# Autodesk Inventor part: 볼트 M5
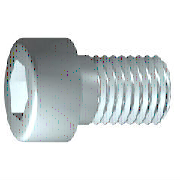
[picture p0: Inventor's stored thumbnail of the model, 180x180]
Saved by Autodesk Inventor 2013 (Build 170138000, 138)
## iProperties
IsCustomPart: 0
Created: 2015-11
Part Number: 볼트 M5
Material: 스테인리스강
Description: 6각머리 태핑 나사
Document SubType Name: Modeling
Standard: KS B 1003
Designer: mdu
Standards Organization: KS
Language: ko-KR
Size Designation: M 5 x 20
Categories: <MemberInstance><Categories><Category DisplayName="조임쇠" InternalName="e4da775c-781d-43d5-af7c-5136215cf5a6" Mnemonic="FSTN"><Category DisplayName="볼트" InternalN
Density: 1 g/cm^3
Author: mdu
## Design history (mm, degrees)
sketch "스케치1"
  geometry: L1 (-1.167, 0)-(20, 0); L2 (20, 0)-(20, 2.5); L3 (20, 2.5)-(2, 2.5); L4 (2, 2.5)-(1.509, 2.5); L5 (1.509, 2.5)-(0, 2.5); L6 (0, 2.5)-(0, 4.25); L7 (0, 4.25)-(-5, 4.25); L8 (-5, 4.25)-(-5, 2.309); L9 (-5, 2.309)-(-2.5, 2.309); L10 (-2.5, 2.309)-(-1.167, 0); L11 (-10, 0)-(25, 0) reference; L12 (0, -0.85)-(0, 5.1) reference; L13 (2, 2.5)-(0, 2.5)
  constraints: 22 end point, 6 parallel, 2 collinear, 2 perpendicular, 1 horizontal, 1 point on line
  dimensions: "d1" = 18 distance from line of L3.end L2 (= GEL); "d2" = 0.49086 distance of L4.end L3.end (computed from GAL); "d3" = 5 distance between parallel lines of L8 L6 (= KOH); "d4" = 2.5 distance of L8.end L9.end (= INTI); "d5" = 60 deg angle of L10 L1; "d6" = 5 diameter of L3 L1 (= GD); "d7" = 5 diameter of L5 L1 (= BDM); "d8" = 4.6188 diameter of L9 L1 (= 1.1547 x SW); "d9" = 8.5 diameter of L7 L1 (= KOD); "d26" = 20 distance between parallel lines of L12 L2 (= NLG)
revolve "본체" sketch "스케치1" stored, may be unused: angle "d10" = 90 deg
sketch "스케치2"
  geometry: L1 (0, -5.95)-(0, 5.95) reference; L2 (-5.95, 0)-(5.95, 0) reference; L3 (2.309, 0)-(1.155, -2); L4 (1.155, -2)-(-1.155, -2); L5 (-1.155, -2)-(-2.309, 0); L6 (-2.309, 0)-(-1.155, 2); L7 (-1.155, 2)-(1.155, 2); L8 (1.155, 2)-(2.309, 0); 2 further points
  constraints: 12 end point, 1 coincident, 1 horizontal alignment, 1 point on line, 12 other
extrude "슬롯" join sketch "스케치2" stored distance "d11" = 10; taper "d12" = 0 deg
workplane "Work Plane1"
fillet "Fillet2" dims "d30" = 0.1 (= R)
body "Solid1"
fillet "모깎기1" dims "d17" = 0.5 (= RR)
feature "스레드" dims "d13" = 18 (= GEL), "d14" = 0
chamfer "모따기1" distance "d15" = 0.49076 (= -0.5 x SPD + 0.5 x GD); stored, may be unused: second distance "d16" = 0.49076 (= GUL), angle "d27" = 45 deg
other parameters: "GD" = 5 (= NND) [user parameter; used in 2 equation terms], "NLG" = 20 [user parameter; used in 1 equation term], "GEL" = 18 [user parameter; used in 2 equation terms], "KOD" = 8.5 [user parameter; used in 1 equation term], "KOH" = 5 [user parameter; used in 1 equation term], "INTI" = 2.5 [user parameter; used in 1 equation term], "GAL" = 0.49076 (= 0.61345 x PTC) [user parameter; used in 1 equation term], "GUL" = 0.49076 (= 0.61345 x PTC) [user parameter; used in 1 equation term], "BDM" = 5 (= NND) [user parameter; used in 1 equation term], "SW" = 4 [user parameter; used in 2 equation terms], "RR" = 0.5 [user parameter; used in 1 equation term], "SPD" = 4.01848 (= NND - 1.2269 x PTC) [user parameter; used in 1 equation term], "d19" = 0, "d28" = 0, "d29" = 0, "R" = 0.1 [user parameter; used in 1 equation term], "PHH" = 0.2 [user parameter], "GD1" = 4.01848 (= THREADDIA - 1.2269 x PTC) [user parameter], "THREADDIA" = 5 [user parameter; used in 1 equation term], "FAWI" = 45 deg [user parameter], "TPU" = 12.5 (computed from PTC) [user parameter], "PTC" = 0.8 [user parameter; used in 5 equation terms], "NND" = 5 [user parameter; used in 3 equation terms], "TOA" = 30 deg [user parameter], "E0" = 4.62 (= 1.155 x SW) [user parameter]
